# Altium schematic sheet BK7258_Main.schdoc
size 408 x 245 mm
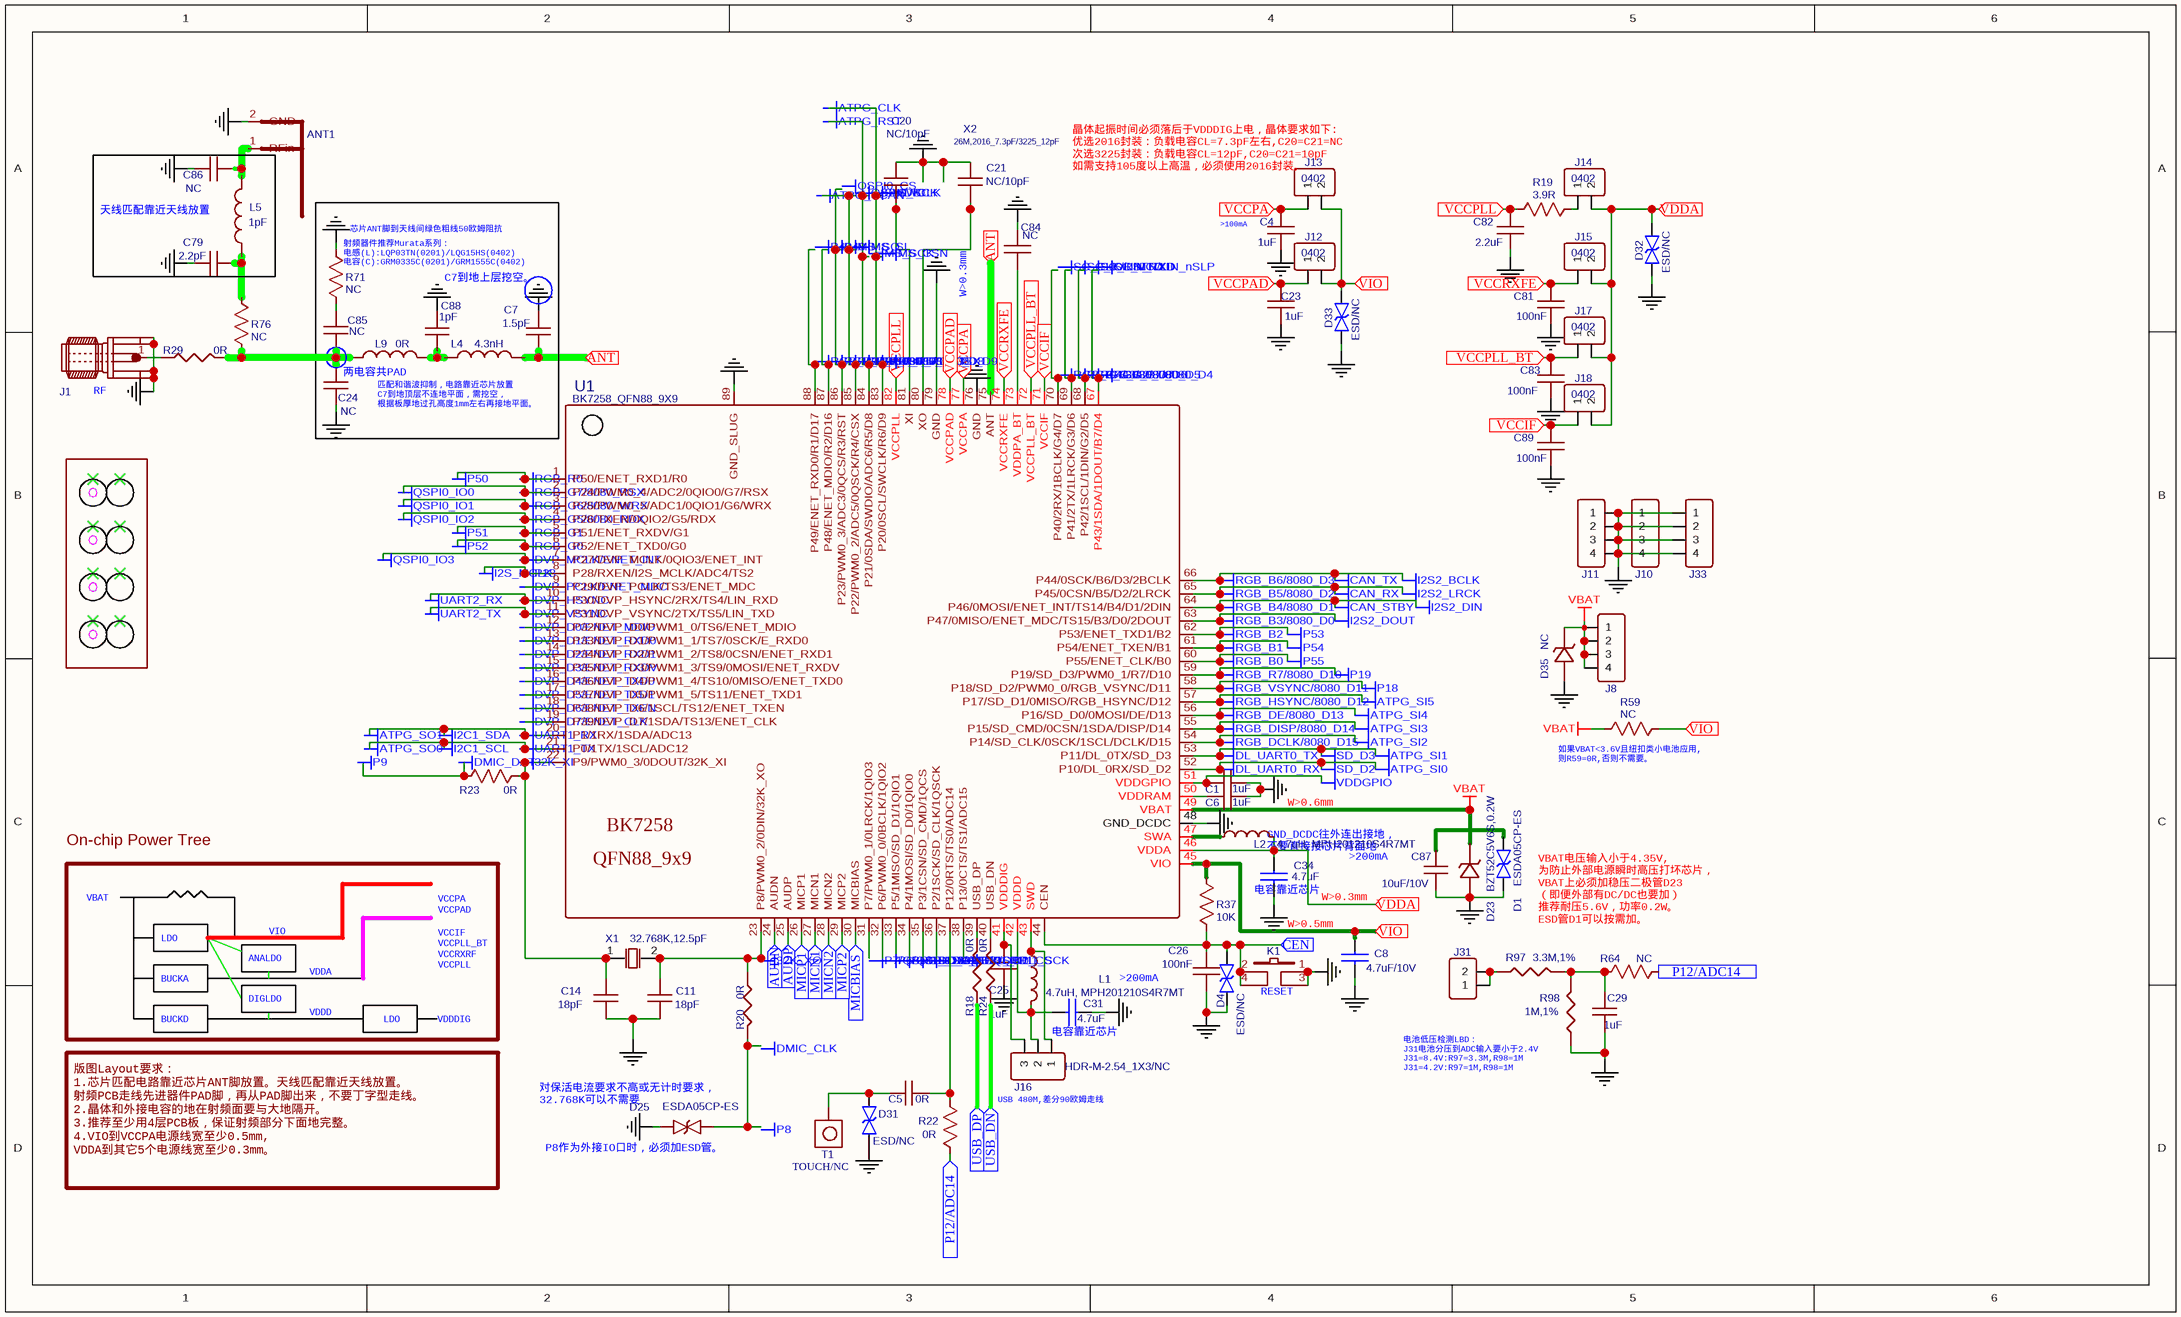
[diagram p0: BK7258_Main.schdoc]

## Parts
ANT1  ANT_PIFA  [ANT_PIFA3_2G4_1MM2_L]  (value not drawn)
C1  1uF  [C0402]
C4  1uF  [C0402]
C5  0R  [C0402]
C6  1uF  [C0402]
C7  1.5pF  [C0201]
C8  4.7uF/10V  [C0603]
C11  18pF  [C0201]
C14  18pF  [C0201]
C20  NC/10pF  [C0201]
C21  NC/10pF  [C0201]
C23  1uF  [C0402]
C24  NC  [C0201]
C25  1uF  [C0402]
C26  100nF  [C0402]
C29  1uF  [C0402]
C31  4.7uF  [C0603]
C34  4.7uF  [C0603]
C79  2.2pF  [C0201]
C81  100nF  [C0402]
C82  2.2uF  [C0402]
C83  100nF  [C0402]
C84  NC  [C0402]
C85  NC  [C0201]
C86  NC  [C0201]
C87  10uF/10V  [C0603]
C88  1pF  [C0201]
C89  100nF  [C0402]
D1  ESDA05CP-ES  [DFN1006-2L-BI]
D4  ESD/NC  [ESD0402]
D23  BZT52C5V6S,0.2W  [SOD-323_L1.8-W1.3-LS2.5-RD]
D25  ESDA05CP-ES  [ESD0402]
D31  ESD/NC  [ESD0402]
D32  ESD/NC  [ESD0402]
D33  ESD/NC  [ESD0402]
D35  NC  [SMA_L4.3-W2.7-LS5.1-RD]
J1  SMA_SMD_5PIN_50OHM  [SMA_SMD_5PIN_50OHM]  (value not drawn)
J8  HDR-M-2.54_1x4  [HDR-M-2.54_1X4]  (value not drawn)
J10  HDR-M-2.54_1x4  [HDR-M-2.54_1X4]  (value not drawn)
J11  HDR-M-2.54_1x4  [HDR-M-2.54_1X4]  (value not drawn)
J12  HDR-M-2.54_1X2_0402  [HDR-M-2.54_1X2_0402]  (value not drawn)
J13  HDR-M-2.54_1X2_0402  [HDR-M-2.54_1X2_0402]  (value not drawn)
J14  HDR-M-2.54_1X2_0402  [HDR-M-2.54_1X2_0402]  (value not drawn)
J15  HDR-M-2.54_1X2_0402  [HDR-M-2.54_1X2_0402]  (value not drawn)
J16  HDR-M-2.54_1X3/NC  [HDR-M-2.54_1X3]
J17  HDR-M-2.54_1X2_0402  [HDR-M-2.54_1X2_0402]  (value not drawn)
J18  HDR-M-2.54_1X2_0402  [HDR-M-2.54_1X2_0402]  (value not drawn)
J31  HDR-M-2.54_1x2  [HDR-M-2.54_1X2]  (value not drawn)
J33  HDR-M-2.54_1x4  [HDR-M-2.54_1X4]  (value not drawn)
K1  KEY  [4PIN_SWITCH_SMD_4.5MM]  (value not drawn)
L1  4.7uH, MPH201210S4R7MT  [L0805]
L2  4.7uH, MPH201210S4R7MT  [L0805]
L4  4.3nH  [L0201]
L5  1pF  [L0201]
L9  0R  [L0201]
MK1  MARK  [MARK]  (value not drawn)
MK2  MARK  [MARK]  (value not drawn)
MK3  MARK  [MARK]  (value not drawn)
MK4  MARK  [MARK]  (value not drawn)
R18  0R  [R0201]
R19  3.9R  [R0402]
R20  0R  [R0201]
R22  0R  [R0201]
R23  0R  [R0201]
R24  0R  [R0201]
R29  0R  [R0201]
R37  10K  [R0402]
R59  NC  [R0402]
R64  NC  [R0402]
R71  NC  [R0201]
R76  NC  [R0201]
R97  3.3M,1%  [R0402]
R98  1M,1%  [R0402]
T1  TOUCH/NC  [TP4X0_TOUCH_UPDATED]
U1  BK7258_QFN88_9X9  [QFN88_9X9_BK7258]
X1  32.768K,12.5pF  [3215]
X2  26M,2016_7.3pF/3225_12pF  [3225_2016]

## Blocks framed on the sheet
天线匹配靠近天线放置: C79 C86 L5

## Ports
ANT (in), AUDN (in), AUDP (in), CEN (in), MICBIAS (in), MICN1 (in), MICN2 (in), MICP1 (in), MICP2 (in), P12/ADC14 (in), USB_DN (in), USB_DP (in), VCCIF (in), VCCPA (in), VCCPAD (in), VCCPLL (in), VCCPLL_BT (in), VCCRXFE (in), VDDA (in), VIO (in)

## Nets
ATPG_SI0: U1.52(P10/DL_0RX/SD_D2)  [also labelled DL_UART0_RX, SD_D2]
ATPG_SI1: U1.53(P11/DL_0TX/SD_D3)  [also labelled DL_UART0_TX, SD_D3]
ATPG_SI2: U1.54(P14/SD_CLK/0SCK/1SCL/DCLK/D15)  [also labelled RGB_DCLK/8080_D15]
ATPG_SI3: U1.55(P15/SD_CMD/0CSN/1SDA/DISP/D14)  [also labelled RGB_DISP/8080_D14]
ATPG_SI4: U1.56(P16/SD_D0/0MOSI/DE/D13)  [also labelled RGB_DE/8080_D13]
ATPG_SI5: U1.57(P17/SD_D1/0MISO/RGB_HSYNC/D12)  [also labelled RGB_HSYNC/8080_D12]
CAN_RX: U1.65(P45/0CSN/B5/D2/2LRCK)  [also labelled I2S2_LRCK, RGB_B5/8080_D2]
CAN_STBY: U1.64(P46/0MOSI/ENET_INT/TS14/B4/D1/2DIN)  [also labelled I2S2_DIN, RGB_B4/8080_D1]
CAN_TX: U1.66(P44/0SCK/B6/D3/2BCLK)  [also labelled I2S2_BCLK, RGB_B6/8080_D3]
GGND: ANT1.2(GND) C1.1 C4.1 C6.1 C7.2 C8.2 C11.2 C14.2 C20.1 C21.1 C23.1 C24.1 C25.1 C26.2 C29.2 C31.1 C34.2 C79.1 C81.1 C82.1 C83.1 C84.1 C86.1 C87.2 C88.2 C89.1 D1.1 D4.2 D23.2(A) D25.2 D31.2 D32.2 D33.2 D35.2(A) J1.2(RF) J1.3(RF) J1.4(RF) J1.5(RF) J10.1 J10.2 J10.3 J10.4 J11.1 J11.2 J11.3 J11.4 J33.1 J33.2 J33.3 J33.4 K1.1 K1.3 R71.2 R98.2 U1.48(GND_DCDC) U1.76(GND) U1.79(GND) U1.89(GND_SLUG)
I2S2_DOUT: U1.63(P47/0MISO/ENET_MDC/TS15/B3/D0/2DOUT)  [also labelled RGB_B3/8080_D0]
P18: U1.58(P18/SD_D2/PWM0_0/RGB_VSYNC/D11)  [also labelled RGB_VSYNC/8080_D11]
P19: U1.59(P19/SD_D3/PWM0_1/R7/D10)  [also labelled RGB_R7/8080_D10]
P53: U1.62(P53/ENET_TXD1/B2)  [also labelled RGB_B2]
P54: U1.61(P54/ENET_TXEN/B1)  [also labelled RGB_B1]
P55: U1.60(P55/ENET_CLK/B0)  [also labelled RGB_B0]
VBAT: D23.1(K) D35.1(K) J8.1 J8.2 J8.3 J8.4 R59.2 U1.49(VBAT)
VDDGPIO: C1.2 U1.51(VDDGPIO)
ANT: C7.1 L4.2 U1.75(ANT) ; port ANT
AUDN: U1.24(AUDN) ; port AUDN
AUDP: U1.25(AUDP) ; port AUDP
CEN: C26.1 D4.1 K1.2 K1.4 R37.2 U1.44(CEN) ; port CEN
MICBIAS: U1.30(MICBIAS) ; port MICBIAS
MICN1: U1.27(MICN1) ; port MICN1
MICN2: U1.28(MICN2) ; port MICN2
MICP1: U1.26(MICP1) ; port MICP1
MICP2: U1.29(MICP2) ; port MICP2
P12/ADC14: R22.1 R64.1 ; port P12/ADC14
USB_DN: R24.2 ; port USB_DN
USB_DP: R18.2 ; port USB_DP
VCCIF: C89.2 J18.1 U1.71(VCCIF) ; port VCCIF
VCCPA: C4.2 J13.1 U1.77(VCCPA) ; port VCCPA
VCCPAD: C23.2 J12.1 U1.78(VCCPAD) ; port VCCPAD
VCCPLL: C82.2 R19.2 U1.82(VCCPLL) ; port VCCPLL
VCCPLL_BT: C83.2 J17.1 U1.72(VCCPLL_BT) ; port VCCPLL_BT
VCCRXFE: C81.2 J15.1 U1.74(VCCRXFE) ; port VCCRXFE
VDDA: C34.1 D32.1 J14.2 J15.2 J17.2 J18.2 L2.2 U1.46(VDDA) ; port VDDA
VIO: C8.1 D33.1 J12.2 J13.2 R37.1 R59.1 U1.45(VIO) ; port VIO
NetANT1_1: ANT1.1(RFin) C86.2 L5.2
NetC5_1: C5.1 D31.1 T1.1
NetC5_2: C5.2 R22.2 U1.37(P12/0RTS/TS0/ADC14)
NetC6_2: C6.2 U1.50(VDDRAM)
NetC11_1: C11.1 R20.1 U1.23(P8/PWM0_2/0DIN/32K_XO) X1.2(OSC2)
NetC14_1: C14.1 R23.1 U1.22(P9/PWM0_3/0DOUT/32K_XI) X1.1(OSC1)
NetC20_2: C20.2 U1.81(XI)
NetC21_2: C21.2 U1.80(XO)
NetC24_2: C24.2 C85.2 L9.1 R29.1 R76.1
NetC25_2: C25.2 J16.3 U1.41(VDDDIG)
NetC29_1: C29.1 R64.2 R97.1 R98.1
NetC31_2: C31.2 J16.2 L1.2 U1.42(VDDD)
NetC79_2: C79.2 L5.1 R76.2
NetC84_2: C84.2 U1.73(VDDPA_BT)
NetC85_1: C85.1 R71.1
NetC87_1: C87.1 D1.2
NetC88_1: C88.1 L4.1 L9.2
NetD25_1: D25.1 R20.2
NetJ1_1: J1.1(RF) R29.2
NetJ14_1: J14.1 R19.1
NetJ16_1: J16.1 L1.1 U1.43(SWD)
NetJ31_1: J31.1 J31.2 R97.2
NetL2_1: L2.1 U1.47(SWA)
NetR18_1: R18.1 U1.39(USB_DP)
NetR24_1: R24.1 U1.40(USB_DN)

Not connected (* = marked no-connect by the designer): MK1 1* 2*; MK2 1* 2*; MK3 1* 2*; MK4 1* 2*; R23 2; U1 1(P50/ENET_RXD1/R0) 2(P24/PWM0_4/ADC2/0QIO0/G7/RSX) 3(P25/PWM0_5/ADC1/0QIO1/G6/WRX) 4(P26/TXEN/0QIO2/G5/RDX) 5(P51/ENET_RXDV/G1) 6(P52/ENET_TXD0/G0) 7(P27/DVP_MCLK/0QIO3/ENET_INT) 8(P28/RXEN/I2S_MCLK/ADC4/TS2) 9(P29/DVP_PCLK/TS3/ENET_MDC) 10(P30/DVP_HSYNC/2RX/TS4/LIN_RXD) 11(P31/DVP_VSYNC/2TX/TS5/LIN_TXD) 12(P32/DVP_D0/PWM1_0/TS6/ENET_MDIO) 13(P33/DVP_D1/PWM1_1/TS7/0SCK/E_RXD0) 14(P34/DVP_D2/PWM1_2/TS8/0CSN/ENET_RXD1) 15(P35/DVP_D3/PWM1_3/TS9/0MOSI/ENET_RXDV) 16(P36/DVP_D4/PWM1_4/TS10/0MISO/ENET_TXD0) 17(P37/DVP_D5/PWM1_5/TS11/ENET_TXD1) 18(P38/DVP_D6/1SCL/TS12/ENET_TXEN) 19(P39/DVP_D7/1SDA/TS13/ENET_CLK) 20(P1/1RX/1SDA/ADC13) 21(P0/1TX/1SCL/ADC12) 31(P7/PWM0_1/0LRCK/1QIO3) 32(P6/PWM0_0/0BCLK/1QIO2) 33(P5/1MISO/SD_D1/1QIO1) 34(P4/1MOSI/SD_D0/1QIO0) 35(P3/1CSN/SD_CMD/1QCS) 36(P2/1SCK/SD_CLK/1QSCK) 38(P13/0CTS/TS1/ADC15) 67(P43/1SDA/1DOUT/B7/D4) 68(P42/1SCL/1DIN/G2/D5) 69(P41/2TX/1LRCK/G3/D6) 70(P40/2RX/1BCLK/G4/D7) 83(P20/0SCL/SWCLK/R6/D9) 84(P21/0SDA/SWDIO/ADC6/R5/D8) 85(P22/PWM0_2/ADC5/0QSCK/R4/CSX) 86(P23/PWM0_3/ADC3/0QCS/R3/RST) 87(P48/ENET_MDIO/R2/D16) 88(P49/ENET_RXD0/R1/D17)

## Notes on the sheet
- 晶体起振时间必须落后于VDDDIG上电，晶体要求如下:
  优选2016封装：负载电容CL=7.3pF左右,C20=C21=NC
  次选3225封装：负载电容CL=12pF,C20=C21=10pF
  如需支持105度以上高温，必须使用2016封装。
- 射频器件推荐Murata系列：
  电感(L):LQP03TN(0201)/LQG15HS(0402)
  电容(C):GRM0335C(0201)/GRM1555C(0402)
- (near R71) 芯片ANT脚到天线间绿色粗线50欧姆阻抗
- (near C4) >100mA
- C7到地上层挖空。
- W>0.3mm
- (near J1) RF
- 两电容共PAD
- 匹配和谐波抑制，电路靠近芯片放置
  C7到地顶层不连地平面，需挖空，
  根据板厚地过孔高度1mm左右再接地平面。
- (near R59) 如果VBAT<3.6V且纽扣类小电池应用,
  则R59=0R,否则不需要。
- On-chip Power Tree
- GND_DCDC往外连出接地，
  不要直接接芯片背面地
- (near L2) W>0.6mm
- >200mA
- VBAT电压输入小于4.35V,
  为防止外部电源瞬时高压打坏芯片，
  VBAT上必须加稳压二极管D23
  （即便外部有DC/DC也要加）
  推荐耐压5.6V，功率0.2W。
  ESD管D1可以按需加。
- VBAT
- VIO
- (near U1) VCCPA
  VCCPAD
- (near U1) VCCIF
  VCCPLL_BT
  VCCRXRF
  VCCPLL
- (near C34) 电容靠近芯片
- W>0.5mm
- LDO
- BUCKA
- ANALDO
- DIGLDO
- VDDA
- (near K1) RESET
- 版图Layout要求：
  1.芯片匹配电路靠近芯片ANT脚放置。天线匹配靠近天线放置。
  射频PCB走线先进器件PAD脚，再从PAD脚出来，不要丁字型走线。
  2.晶体和外接电容的地在射频面要与大地隔开。
  3.推荐至少用4层PCB板，保证射频部分下面地完整。
  4.VIO到VCCPA电源线宽至少0.5mm,
  VDDA到其它5个电源线宽至少0.3mm。
- BUCKD
- VDDD
- VDDDIG
- 电容靠近芯片
- 电池低压检测LBD：
  J31电池分压到ADC输入要小于2.4V
  J31=8.4V:R97=3.3M,R98=1M
  J31=4.2V:R97=1M,R98=1M
- (near D25) 对保活电流要求不高或无计时要求，
  32.768K可以不需要
- (near D25) P8作为外接IO口时，必须加ESD管。
- USB 480M,差分90欧姆走线
- Labels drawn without touching a wire or pin: 32K_XI, 32K_XO, ATPG_CLK, ATPG_RST, ATPG_SCAN, ATPG_SO0, ATPG_SO1, DMIC_CLK, DMIC_DAT, DVP_D0/ENET_MDIO, DVP_D1/ENET_RXD0, DVP_D2/ENET_RXD1, DVP_D3/ENET_RXDV, DVP_D4/ENET_TXD0, DVP_D5/ENET_TXD1, DVP_D6/ENET_TXEN, DVP_D7/ENET_CLK, DVP_HSYNC, DVP_MCLK/ENET_INT, DVP_PCLK/ENET_MDC, DVP_VSYNC, I2C1_SCL, I2C1_SDA, I2S_MCLK, MS_CSN, MS_SCK, MS_SI, MS_SO, P5/SD_D1/QSPI1_IO1, P6/QSPI1_IO2, P7/QSPI1_IO3, P8, P9, P13, P28, P48, P49, P50, P51, P52, QSPI0_CS, QSPI0_IO0, QSPI0_IO1, QSPI0_IO2, QSPI0_IO3, QSPI0_SCK, RGB_B7/8080_D4, RGB_G0, RGB_G1, RGB_G2/8080_D5, RGB_G3/8080_D6, RGB_G4/8080_D7, RGB_G5/8080_RDX, RGB_G6/8080_WRX, RGB_G7/8080_RSX, RGB_R0, RGB_R1/8080_D17, RGB_R2/8080_D16, RGB_R3/8080_RST, RGB_R4/8080_CSX, RGB_R5/8080_D8, RGB_R6/8080_D9, SC_CLK/LIN_RXD, SC_IO/LIN_TXD, SC_RSTN/LIN_nSLP, SC_VCC, SD_CLK/QSPI1_SCK, SD_CMD/QSPI1_CS, SD_D0/QSPI1_IO0, SWCLK, SWDIO, UART1_RX, UART1_TX, UART2_RX, UART2_TX

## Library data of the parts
ANT1 = ANT_PIFA: Package Display: No
C1 C4 C6 C23 C25 = 1uF: Manufacturer Part Number: 0805ZC105KAT2A; Manufacturer: AVX; APN: C071-0
C5 = 0R: Manufacturer: AVX; Manufacturer Part Number: 06035A101KAT2A; APN: C029-0
C7 = 1.5pF: Manufacturer Part Number: 06035A101KAT2A; Manufacturer: AVX; APN: C029-0
C8 = 4.7uF/10V: Manufacturer Part Number: 0805ZC105KAT2A; Manufacturer: AVX; APN: C071-0
C11 C14 = 18pF: Manufacturer Part Number: 06035A101KAT2A; Manufacturer: AVX; APN: C029-0
C20 C21 = NC/10pF: Manufacturer Part Number: 06035A101KAT2A; Manufacturer: AVX; APN: C029-0
C24 C85 C86 = NC: Manufacturer Part Number: 06035A101KAT2A; Manufacturer: AVX; APN: C029-0
C26 C81 C83 C89 = 100nF: Manufacturer Part Number: 0805ZC105KAT2A; Manufacturer: AVX; APN: C071-0
C29 = 1uF: Manufacturer Part Number: 06035A101KAT2A; Manufacturer: AVX; APN: C029-0
C31 C34 = 4.7uF: Manufacturer Part Number: 0805ZC105KAT2A; Manufacturer: AVX; APN: C071-0
C79 = 2.2pF: Manufacturer Part Number: 06035A101KAT2A; Manufacturer: AVX; APN: C029-0
C82 = 2.2uF: Manufacturer Part Number: 0805ZC105KAT2A; Manufacturer: AVX; APN: C071-0
C84 = NC: Manufacturer Part Number: 0805ZC105KAT2A; Manufacturer: AVX; APN: C071-0
C87 = 10uF/10V: Manufacturer Part Number: 06035A101KAT2A; Manufacturer: AVX; APN: C029-0
C88 = 1pF: Manufacturer Part Number: 06035A101KAT2A; Manufacturer: AVX; APN: C029-0
D1 = ESDA05CP-ES: BOM_Manufacturer: SOT23-5_SGM2019; Contributor: D-MAN
D4 D31-D33 = ESD/NC: Contributor: D-MAN
D23 = BZT52C5V6S,0.2W: Manufacturer: FUXINSEMI(富芯森美); Contributor: LCSC
D25 = ESDA05CP-ES: Contributor: D-MAN
D35 = NC: Contributor: lcsc
J1 = SMA_SMD_5PIN_50OHM: Contributor: guogen.le
J8 J10 J11 J33 = HDR-M-2.54_1x4: Contributor: LCEDA_Lib
J12-J15 J17 J18 = HDR-M-2.54_1X2_0402: Contributor: qunshan.xu
J16 = HDR-M-2.54_1X3/NC: Contributor: LCEDA_Lib
J31 = HDR-M-2.54_1x2: Contributor: LCEDA_Lib
K1 = KEY: Manufacturer Part Number: EP11SD1ABE; Manufacturer: C & K; APN: S001-0
L1 = 4.7uH, MPH201210S4R7MT: Manufacturer: Sunlord(顺络); Manufacturer Part: MPH201210S2R2MT; nameAlias: Value; Contributor: lcsc; 3DModel: L0805_L2.0-W1.6-H0.9
L2 = 4.7uH, MPH201210S4R7MT: Manufacturer: Sunlord(顺络); Manufacturer Part: MPH201210S2R2MT; nameAlias: Value; Contributor: LCSC
L4 = 4.3nH: Manufacturer: COILCRAFT; Manufacturer Part Number: 1008HT-R27TJBC; APN: L914-0
L5 = 1pF: Manufacturer: COILCRAFT; Manufacturer Part Number: 1008HT-R27TJBC; APN: L914-0
L9 = 0R: Manufacturer: COILCRAFT; Manufacturer Part Number: 1008HT-R27TJBC; APN: L914-0
MK1-MK4 = MARK: Contributor: qunshan.xu
R18 R24 = 0R: Manufacturer Part Number: RK73H2AT4752F; Manufacturer: KOA; APN: R096-0
R19 = 3.9R: nameAlias: Value(Ω); Contributor: LCEDA_Lib
R20 R29 = 0R: Manufacturer Part Number: RM73B1JT240J; Manufacturer: KOA; APN: R125-0
R22 R23 = 0R: nameAlias: Value(Ω); Contributor: LCEDA_Lib
R37 = 10K: nameAlias: Value(Ω); Contributor: LCEDA_Lib
R59 R64 R71 R76 = NC: nameAlias: Value(Ω); Contributor: LCEDA_Lib
R97 = 3.3M,1%: Manufacturer Part Number: RM73B1JT240J; Manufacturer: KOA; APN: R125-0
R98 = 1M,1%: Manufacturer Part Number: RM73B1JT240J; Manufacturer: KOA; APN: R125-0
T1 = TOUCH/NC: Manufacturer Part Number: PGM01SS-G59; Manufacturer: Crane; APN: TP01-0
U1 = BK7258_QFN88_9X9: Contributor: qunshan.xu
X1 = 32.768K,12.5pF: BOM_Manufacturer: YXC; BOM_Manufacturer Part: X49SM1431818MSD2SC; nameAlias: Frequency
X2 = 26M,2016_7.3pF/3225_12pF: Contributor: qunshan.xu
